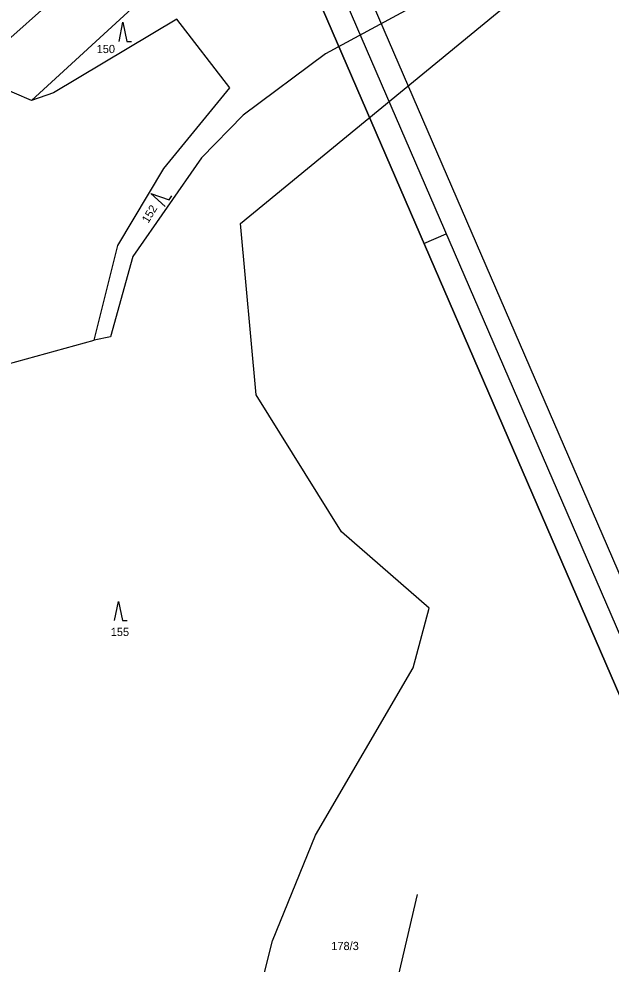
# Model space of a CAD drawing. Extents: x -866656 to -858817, y -1041816 to -1038653.
# Drawn here: x -864878.1 to -864755.3, y -1040943.1 to -1040747.1 of the extents above; entities that cross this region are included whole.
import ezdxf

# ---------------------------------------------------------------- set-up
doc = ezdxf.new("R2010")
doc.units = 0
doc.layers.add('tisk ramy', color=7, linetype='Continuous')
doc.layers.add('Vrstva 1', color=7, linetype='Continuous')

msp = doc.modelspace()

# ---------------------------------------------------------------- linework, layer by layer
at = {"layer": 'tisk ramy'}
msp.add_line((-864794.13, -1040793.62), (-864789.54, -1040791.63), dxfattribs=at)
for points in [[(-865732.63, -1039823.16), (-864894.8, -1040764.23), (-864672.98, -1040566.75), (-865510.81, -1039625.68)], [(-865224.28, -1040522.07), (-864724.07, -1041678.52), (-864451.49, -1041560.62), (-864951.69, -1040404.17)], [(-864954.3, -1040410.74), (-864458.06, -1041558.01), (-864721.47, -1041671.94), (-865217.7, -1040524.67)], [(-865211.14, -1040527.28), (-864800.25, -1041477.22), (-864546.01, -1041367.26), (-864956.9, -1040417.31)], [(-864956.9, -1040417.31), (-864546.01, -1041367.26), (-864800.25, -1041477.22), (-865211.14, -1040527.28)]]:
    msp.add_lwpolyline(points, close=True, dxfattribs=at)
at = {"layer": 'Vrstva 1'}
for p, q in [((-864778.45, -1040734.78), (-864814.5, -1040754.28)), ((-864875.45, -1040763.96), (-864851.58, -1040742.03)), ((-864832.12, -1040789.49), (-864776.97, -1040744.19)), ((-864845.3, -1040747.09), (-864870.86, -1040762.38)), ((-864834.35, -1040761.33), (-864845.3, -1040747.09)), ((-864857.31, -1040751.75), (-864856.51, -1040747.75)), ((-864856.51, -1040747.75), (-864855.71, -1040751.75)), ((-864855.71, -1040751.75), (-864854.71, -1040751.75)), ((-864814.5, -1040754.28), (-864831.58, -1040767.03)), ((-864875.45, -1040763.96), (-864887.56, -1040758.79)), ((-864847.99, -1040778.12), (-864834.35, -1040761.33)), ((-864870.86, -1040762.38), (-864875.45, -1040763.96)), ((-864831.58, -1040767.03), (-864840.19, -1040775.9)), ((-864840.19, -1040775.9), (-864854.44, -1040796.35)), ((-864857.54, -1040794.09), (-864847.99, -1040778.12)), ((-864847.72, -1040785.99), (-864850.74, -1040783.25)), ((-864850.74, -1040783.25), (-864846.9, -1040784.61)), ((-864846.9, -1040784.61), (-864846.38, -1040783.76)), ((-864828.89, -1040825.04), (-864832.12, -1040789.49)), ((-864862.46, -1040813.72), (-864857.54, -1040794.09)), ((-864854.44, -1040796.35), (-864859.11, -1040813.02)), ((-864920.38, -1040829.5), (-864862.46, -1040813.72)), ((-864859.11, -1040813.02), (-864862.46, -1040813.72)), ((-864811.22, -1040853.42), (-864828.89, -1040825.04)), ((-864793.02, -1040869.29), (-864811.22, -1040853.42)), ((-864858.22, -1040871.86), (-864857.42, -1040867.86)), ((-864857.42, -1040867.86), (-864856.62, -1040871.86)), ((-864796.34, -1040881.64), (-864793.02, -1040869.29)), ((-864856.62, -1040871.86), (-864855.62, -1040871.86)), ((-864816.6, -1040916.32), (-864796.34, -1040881.64)), ((-864825.48, -1040938.24), (-864816.6, -1040916.32)), ((-864808.36, -1040983.3), (-864795.43, -1040928.67)), ((-864829.43, -1040953.64), (-864825.48, -1040938.24))]:
    msp.add_line(p, q, dxfattribs=at)

# ---------------------------------------------------------------- texts
for s, p in [('150', (-864861.94, -1040754.15)), ('155', (-864859.02, -1040875.05)), ('178/3', (-864813.31, -1040940.18))]:
    msp.add_text(s, height=1.7, dxfattribs=at).set_placement(p)
msp.add_text('152', height=1.7, rotation=59.1181, dxfattribs=at).set_placement((-864851.24, -1040789.56))

doc.saveas('drawing.dxf')
